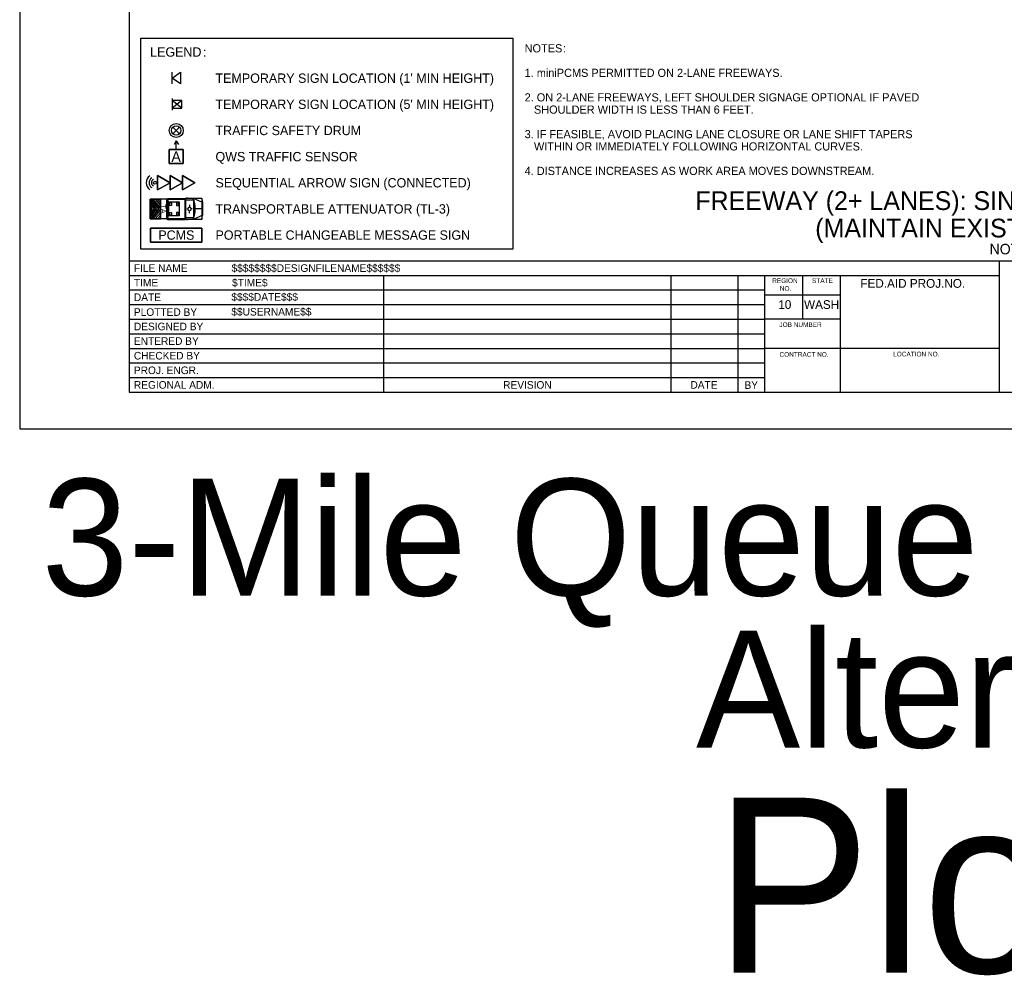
# Model space of a CAD drawing. Extents: x 99999 to 100116, y 99995 to 100013.
# Drawn here: x 100019.06 to 100027.5, y 99995.01 to 100003.19 of the extents above; entities that cross this region are included whole.
import ezdxf

# ---------------------------------------------------------------- set-up
doc = ezdxf.new("R2010")
doc.units = 0
for name, color, linetype in [('SH_DE_DetailHeading1Text', 7, 'Continuous'), ('SH_GI_GeneralNotesBodyText', 7, 'Continuous'), ('SH_GI_PlotLimits', 7, 'Continuous'), ('SH_GI_SheetBorder', 7, 'Continuous'), ('SH_GI_SheetLocationText', 7, 'Continuous'), ('SH_GI_SheetTextInCells', 7, 'Continuous'), ('SH_GI_TitleBlockText', 7, 'Continuous'), ('TR_WZ_PCMS', 7, 'Continuous'), ('TR_WZ_PortableSignMount5ftMinBlk-Wht', 7, 'Continuous'), ('TR_WZ_PortableSignMountBlk-Wht', 7, 'Continuous'), ('TR_WZ_SequentialArrowSign', 7, 'Continuous'), ('TR_WZ_TrafficSafetyDrum', 7, 'Continuous'), ('TR_WZ_TransportableAttenuator', 7, 'Continuous'), ('TR_WZ_WorkZoneDetails', 7, 'Continuous'), ('TR_WZ_WorkZoneTextCurrent', 7, 'Continuous')]:
    doc.layers.add(name, color=color, linetype=linetype)

msp = doc.modelspace()

# ---------------------------------------------------------------- linework, layer by layer
at = {"layer": 'SH_GI_PlotLimits'}
msp.add_lwpolyline([(100019.0625, 99999.6875), (100036.0625, 99999.6875), (100036.0625, 100010.6875), (100019.0625, 100010.6875)], close=True, dxfattribs=at)
at = {"layer": 'SH_GI_SheetBorder'}
for p, q in [((100020, 100010.375), (100020, 100000)), ((100020, 100001.1259), (100035.75, 100001.1259)), ((100027.4566, 100000), (100027.4566, 100001.1259)), ((100020, 100001.0008), (100027.4566, 100001.0008)), ((100022.179, 100001.0008), (100022.179, 100000)), ((100024.641, 100001.0008), (100024.641, 100000)), ((100025.2164, 100001.0008), (100025.2164, 100000)), ((100025.4451, 100001.0008), (100025.4451, 100000)), ((100025.7719, 100000.6255), (100025.7719, 100001.0008)), ((100026.0956, 100000), (100026.0956, 100001.0008)), ((100020, 100000.8757), (100022.1821, 100000.8757)), ((100022.1821, 100000.8757), (100025.4466, 100000.8757)), ((100026.0958, 100000.831), (100025.4466, 100000.831)), ((100020, 100000.7506), (100022.1821, 100000.7506)), ((100022.1821, 100000.7506), (100025.4466, 100000.7506)), ((100020, 100000.6255), (100025.4466, 100000.6255)), ((100026.0958, 100000.6255), (100025.4466, 100000.6255)), ((100020, 100000.5004), (100025.4466, 100000.5004)), ((100020, 100000.3753), (100025.4466, 100000.3753)), ((100027.4566, 100000.3753), (100025.4466, 100000.3753)), ((100020, 100000.2502), (100025.4466, 100000.2502)), ((100020, 100000.1251), (100025.4466, 100000.1251)), ((100020, 100000), (100035.75, 100000))]:
    msp.add_line(p, q, dxfattribs=at)
at = {"layer": 'TR_WZ_PCMS'}
for points in [[(100020.6241, 100001.4059), (100020.6241, 100001.2859), (100020.1841, 100001.2859), (100020.1841, 100001.4059), (100020.6241, 100001.4059)], [(100020.1841, 100001.4059), (100020.1841, 100001.2859), (100020.6241, 100001.2859), (100020.6241, 100001.4059), (100020.1841, 100001.4059)]]:
    msp.add_lwpolyline(points, dxfattribs=at)
at = {"layer": 'TR_WZ_PortableSignMount5ftMinBlk-Wht'}
for p, q in [((100020.3682, 100002.5159), (100020.3682, 100002.4159)), ((100020.4516, 100002.4334), (100020.3682, 100002.4984)), ((100020.4516, 100002.4984), (100020.3682, 100002.4334)), ((100020.4099, 100002.4659), (100020.4099, 100002.4659)), ((100020.41, 100002.4658), (100020.41, 100002.4658))]:
    msp.add_line(p, q, dxfattribs=at)
msp.add_lwpolyline([(100020.4516, 100002.4334), (100020.4516, 100002.4984), (100020.3682, 100002.4984), (100020.3682, 100002.4334)], close=True, dxfattribs=at)
at = {"layer": 'TR_WZ_PortableSignMountBlk-Wht'}
msp.add_line((100020.3682, 100002.64), (100020.3682, 100002.74), dxfattribs=at)
msp.add_lwpolyline([(100020.3682, 100002.6899), (100020.44, 100002.74), (100020.44, 100002.64)], close=True, dxfattribs=at)
at = {"layer": 'TR_WZ_SequentialArrowSign'}
for points in [[(100020.3508, 100001.7939), (100020.2441, 100001.7321), (100020.2441, 100001.8557), (100020.3508, 100001.7939)], [(100020.2441, 100001.8557), (100020.2441, 100001.7321), (100020.3508, 100001.7939), (100020.2441, 100001.8557)], [(100020.4575, 100001.7939), (100020.3508, 100001.7321), (100020.3508, 100001.7939), (100020.3508, 100001.8557), (100020.4575, 100001.7939)], [(100020.3508, 100001.8557), (100020.3508, 100001.7939), (100020.3508, 100001.7321), (100020.4575, 100001.7939), (100020.3508, 100001.8557)], [(100020.5641, 100001.7939), (100020.4575, 100001.7321), (100020.4575, 100001.7939), (100020.4575, 100001.8557), (100020.5641, 100001.7939)], [(100020.4575, 100001.8557), (100020.4575, 100001.7939), (100020.4575, 100001.7321), (100020.5641, 100001.7939), (100020.4575, 100001.8557)]]:
    msp.add_lwpolyline(points, dxfattribs=at)
msp.add_circle((100020.2216, 100001.7939), 0.0125, dxfattribs=at)
for radius, start, end in [(0.075, 127.32912, 232.67088), (0.05, 123.97816, 236.02184), (0.03, 117.15796, 242.84204)]:
    msp.add_arc((100020.2216, 100001.7939), radius, start, end, dxfattribs=at)
at = {"layer": 'TR_WZ_TrafficSafetyDrum'}
for p, q in [((100020.4324, 100002.2701), (100020.3758, 100002.2136)), ((100020.4324, 100002.2136), (100020.3758, 100002.2701))]:
    msp.add_line(p, q, dxfattribs=at)
for radius in [0.06, 0.06, 0.04]:
    msp.add_circle((100020.4041, 100002.2419), radius, dxfattribs=at)
at = {"layer": 'TR_WZ_TransportableAttenuator'}
for p, q in [((100020.1791, 100001.6385), (100020.2355, 100001.5706)), ((100020.1791, 100001.6167), (100020.1791, 100001.6385)), ((100020.2355, 100001.5706), (100020.1791, 100001.6385)), ((100020.1791, 100001.6385), (100020.1791, 100001.6167)), ((100020.2551, 100001.5701), (100020.185, 100001.6546)), ((100020.185, 100001.6546), (100020.2041, 100001.6546)), ((100020.185, 100001.6546), (100020.2551, 100001.5701)), ((100020.2041, 100001.6546), (100020.185, 100001.6546)), ((100020.2041, 100001.6546), (100020.2676, 100001.5776)), ((100020.2676, 100001.5776), (100020.2041, 100001.6546)), ((100020.2676, 100001.6025), (100020.2248, 100001.6546)), ((100020.2248, 100001.6546), (100020.2439, 100001.6546)), ((100020.2439, 100001.6546), (100020.2248, 100001.6546)), ((100020.2248, 100001.6546), (100020.2676, 100001.6025)), ((100020.2439, 100001.6546), (100020.2676, 100001.626)), ((100020.2676, 100001.626), (100020.2439, 100001.6546)), ((100020.2676, 100001.4857), (100020.2676, 100001.6546)), ((100020.3279, 100001.6546), (100020.2676, 100001.6546)), ((100020.3208, 100001.6515), (100020.3208, 100001.4884)), ((100020.3241, 100001.657), (100020.3274, 100001.657)), ((100020.3274, 100001.657), (100020.3274, 100001.4829)), ((100020.3279, 100001.6599), (100020.4803, 100001.6599)), ((100020.3279, 100001.6599), (100020.3279, 100001.4799)), ((100020.3279, 100001.6543), (100020.3279, 100001.4857)), ((100020.3323, 100001.6528), (100020.3323, 100001.4871)), ((100020.3323, 100001.6528), (100020.476, 100001.6528)), ((100020.476, 100001.6528), (100020.476, 100001.4871)), ((100020.4803, 100001.6599), (100020.4803, 100001.4799)), ((100020.4824, 100001.6599), (100020.4824, 100001.4799)), ((100020.6223, 100001.6599), (100020.4824, 100001.6599)), ((100020.551, 100001.646), (100020.4824, 100001.646)), ((100020.5014, 100001.6625), (100020.493, 100001.6625)), ((100020.551, 100001.6599), (100020.5421, 100001.646)), ((100020.551, 100001.6599), (100020.551, 100001.4799)), ((100020.5523, 100001.6599), (100020.5523, 100001.4799)), ((100020.6223, 100001.627), (100020.5523, 100001.6599)), ((100020.6223, 100001.6599), (100020.6223, 100001.4799)), ((100020.6223, 100001.6599), (100020.6291, 100001.6236)), ((100020.2174, 100001.5709), (100020.1791, 100001.6167)), ((100020.1791, 100001.6167), (100020.2174, 100001.5709)), ((100020.1791, 100001.5935), (100020.1987, 100001.5702)), ((100020.1791, 100001.5467), (100020.1791, 100001.5935)), ((100020.1987, 100001.5702), (100020.1791, 100001.5935)), ((100020.1791, 100001.5935), (100020.1791, 100001.5467)), ((100020.1791, 100001.5248), (100020.2174, 100001.5709)), ((100020.2174, 100001.5709), (100020.1791, 100001.5248)), ((100020.2355, 100001.5706), (100020.1791, 100001.5027)), ((100020.1791, 100001.5027), (100020.2355, 100001.5706)), ((100020.1987, 100001.5702), (100020.1791, 100001.5467)), ((100020.1791, 100001.5467), (100020.1987, 100001.5702)), ((100020.1849, 100001.4855), (100020.2551, 100001.5701)), ((100020.2551, 100001.5701), (100020.1849, 100001.4855)), ((100020.2676, 100001.5625), (100020.2037, 100001.4855)), ((100020.2037, 100001.4855), (100020.2676, 100001.5625)), ((100020.2676, 100001.626), (100020.2676, 100001.6025)), ((100020.2676, 100001.6025), (100020.2676, 100001.626)), ((100020.2676, 100001.5776), (100020.2676, 100001.5625)), ((100020.2676, 100001.5625), (100020.2676, 100001.5776)), ((100020.3208, 100001.5826), (100020.3274, 100001.5793)), ((100020.3208, 100001.5573), (100020.3274, 100001.5607)), ((100020.3226, 100001.57), (100020.3257, 100001.57)), ((100020.3241, 100001.5725), (100020.3241, 100001.5674)), ((100020.4951, 100001.5701), (100020.5045, 100001.57)), ((100020.507, 100001.5696), (100020.507, 100001.5696)), ((100020.5175, 100001.6056), (100020.5175, 100001.5911)), ((100020.5398, 100001.5701), (100020.5305, 100001.57)), ((100020.6223, 100001.57), (100020.566, 100001.57)), ((100020.6291, 100001.6236), (100020.6291, 100001.5163)), ((100020.1791, 100001.5027), (100020.1791, 100001.5248)), ((100020.1791, 100001.5248), (100020.1791, 100001.5027)), ((100020.2037, 100001.4855), (100020.1849, 100001.4855)), ((100020.1849, 100001.4855), (100020.2037, 100001.4855)), ((100020.2243, 100001.4855), (100020.2676, 100001.5376)), ((100020.2676, 100001.5376), (100020.2243, 100001.4855)), ((100020.2446, 100001.4855), (100020.2243, 100001.4855)), ((100020.2243, 100001.4855), (100020.2446, 100001.4855)), ((100020.2676, 100001.5128), (100020.2446, 100001.4855)), ((100020.2446, 100001.4855), (100020.2676, 100001.5128)), ((100020.2676, 100001.5376), (100020.2676, 100001.5128)), ((100020.2676, 100001.5128), (100020.2676, 100001.5376)), ((100020.3279, 100001.4857), (100020.2676, 100001.4857)), ((100020.3241, 100001.4829), (100020.3274, 100001.4829)), ((100020.3279, 100001.4799), (100020.4803, 100001.4799)), ((100020.3323, 100001.4871), (100020.476, 100001.4871)), ((100020.551, 100001.4939), (100020.4824, 100001.4939)), ((100020.6223, 100001.4799), (100020.4824, 100001.4799)), ((100020.5014, 100001.4774), (100020.493, 100001.4774)), ((100020.5175, 100001.5343), (100020.5175, 100001.5488)), ((100020.5437, 100001.4939), (100020.551, 100001.4799)), ((100020.6223, 100001.5129), (100020.5523, 100001.4799)), ((100020.6223, 100001.4799), (100020.6291, 100001.5163))]:
    msp.add_line(p, q, dxfattribs=at)
for points in [[(100020.2676, 100001.4855), (100020.1791, 100001.4855), (100020.1791, 100001.6546), (100020.2676, 100001.6546)], [(100020.3398, 100001.63), (100020.4298, 100001.63), (100020.4298, 100001.51), (100020.3398, 100001.51)], [(100020.3473, 100001.6225), (100020.3623, 100001.6225), (100020.3623, 100001.6), (100020.3473, 100001.6)], [(100020.4223, 100001.6225), (100020.4073, 100001.6225), (100020.4073, 100001.6), (100020.4223, 100001.6)], [(100020.3473, 100001.54), (100020.3623, 100001.54), (100020.3623, 100001.5175), (100020.3473, 100001.5175)], [(100020.4223, 100001.54), (100020.4073, 100001.54), (100020.4073, 100001.5175), (100020.4223, 100001.5175)]]:
    msp.add_lwpolyline(points, close=True, dxfattribs=at)
msp.add_lwpolyline([(100020.2676, 100001.6546), (100020.1791, 100001.6546), (100020.1791, 100001.4855), (100020.2676, 100001.4857)], dxfattribs=at)
for centre, major_axis, start_param, end_param in [((100020.3241, 100001.6515), (0, 0.00549), 6.283185, 7.853982), ((100020.4523, 100001.5699), (0, 0.1889), 4.215852, 5.209111), ((100020.3241, 100001.4884), (0, -0.00549), 4.712389, 6.283185)]:
    msp.add_ellipse(centre, major_axis=major_axis, ratio=0.60201, start_param=start_param, end_param=end_param, dxfattribs=at)
for centre, major_axis in [((100020.3241, 100001.5699), (0, -0.00254)), ((100020.5175, 100001.5699), (0, -0.0173))]:
    msp.add_ellipse(centre, major_axis=major_axis, ratio=0.60201, dxfattribs=at)
at = {"layer": 'TR_WZ_WorkZoneDetails'}
for p, q in [((100020.4041, 100002.1529), (100020.3854, 100002.1204)), ((100020.4041, 100002.0779), (100020.4041, 100002.1529)), ((100020.4041, 100002.1529), (100020.4229, 100002.1204))]:
    msp.add_line(p, q, dxfattribs=at)
msp.add_lwpolyline([(100020.3441, 100002.0779), (100020.4641, 100002.0779), (100020.4641, 100001.9579), (100020.3441, 100001.9579)], close=True, dxfattribs=at)
msp.add_lwpolyline([(100020.3441, 100002.0779), (100020.3441, 100001.9579), (100020.4641, 100001.9579), (100020.4641, 100002.0779), (100020.4041, 100002.0779), (100020.3441, 100002.0779)], dxfattribs=at)
at = {"layer": 'TR_WZ_WorkZoneTextCurrent'}
msp.add_lwpolyline([(100020.1, 100003.0339), (100023.2886, 100003.0339), (100023.2886, 100001.2259), (100020.1, 100001.2259)], close=True, dxfattribs=at)

# ---------------------------------------------------------------- texts
at = {"layer": 'SH_DE_DetailHeading1Text'}
for s, height, p in [('FREEWAY (2+ LANES): SINGLE LEFT LANE CLOSURE', 0.16, (100024.8508, 100001.5606)), ('(MAINTAIN EXISTING SPEED LIMIT)', 0.16, (100025.8785, 100001.3259)), ('NOT TO SCALE', 0.09, (100027.3725, 100001.1809))]:
    msp.add_text(s, height=height, rotation=360, dxfattribs=at).set_placement(p)
at = {"layer": 'SH_GI_GeneralNotesBodyText'}
for s, p in [('NOTES', (100023.3886, 100002.9106)), (':', (100023.7161, 100002.9106)), ('1. miniPCMS PERMITTED ON 2-LANE FREEWAYS.', (100023.3886, 100002.7006)), ('2. ON 2-LANE FREEWAYS, LEFT SHOULDER SIGNAGE OPTIONAL IF PAVED ', (100023.3886, 100002.4906)), ('SHOULDER WIDTH IS LESS THAN 6 FEET.', (100023.4686, 100002.3856)), ('3. IF FEASIBLE, AVOID PLACING LANE CLOSURE OR LANE SHIFT TAPERS ', (100023.3886, 100002.1756)), ('WITHIN OR IMMEDIATELY FOLLOWING HORIZONTAL CURVES.', (100023.4686, 100002.0706)), ('4. DISTANCE INCREASES AS WORK AREA MOVES DOWNSTREAM.', (100023.3886, 100001.8606))]:
    msp.add_text(s, height=0.07, rotation=360, dxfattribs=at).set_placement(p)
at = {"layer": 'SH_GI_SheetLocationText'}
for s, height, p in [('3-Mile Queue Warning System', 1, (100019.2499, 99998.258)), ('Alternative', 1, (100024.8575, 99996.9562)), ('Plot 2', 1.5, (100025.015, 99995.0267))]:
    msp.add_text(s, height=height, dxfattribs=at).set_placement(p)
at = {"layer": 'SH_GI_SheetTextInCells'}
for s, height, p in [('FILE NAME', 0.06505, (100020.041, 100001.0308)), ('TIME', 0.06505, (100020.041, 100000.9057)), ('REGION', 0.04003, (100025.5099, 100000.9352)), ('STATE', 0.04003, (100025.8511, 100000.9357)), ('FED.AID PROJ.NO.', 0.07506, (100026.2652, 100000.8945)), ('NO.', 0.04003, (100025.5752, 100000.869)), ('DATE', 0.06505, (100020.041, 100000.7806)), ('PLOTTED BY', 0.06505, (100020.041, 100000.6538)), ('10', 0.07506, (100025.5621, 100000.7131)), ('WASH', 0.07506, (100025.7826, 100000.7131)), ('DESIGNED BY', 0.065052, (100020.041, 100000.5304)), ('JOB NUMBER', 0.04003, (100025.5712, 100000.5587)), ('ENTERED BY', 0.06505, (100020.041, 100000.4053)), ('CHECKED BY', 0.06505, (100020.041, 100000.2802)), ('CONTRACT NO.', 0.040032, (100025.5725, 100000.3037)), ('LOCATION NO.', 0.040032, (100026.5465, 100000.3067)), ('PROJ. ENGR.', 0.065052, (100020.041, 100000.1551)), ('REGIONAL ADM.', 0.065052, (100020.041, 100000.03)), ('REVISION', 0.06505, (100023.2048, 100000.03)), ('DATE', 0.06505, (100024.8091, 100000.03)), ('BY', 0.06505, (100025.2725, 100000.0285))]:
    msp.add_text(s, height=height, dxfattribs=at).set_placement(p)
at = {"layer": 'SH_GI_TitleBlockText'}
for s, height, p in [('$$$$$$$$DESIGNFILENAME$$$$$$', 0.065052, (100020.8775, 100001.0308)), ('$TIME$', 0.06505, (100020.882, 100000.9059)), ('$$$$DATE$$$', 0.065052, (100020.8759, 100000.7835)), ('$$USERNAME$$', 0.065052, (100020.8759, 100000.6567))]:
    msp.add_text(s, height=height, dxfattribs=at).set_placement(p)
at = {"layer": 'TR_WZ_PCMS'}
msp.add_text('PCMS', height=0.08, rotation=360, dxfattribs=at).set_placement((100020.2502, 100001.3059))
at = {"layer": 'TR_WZ_TransportableAttenuator'}
msp.add_text('TA', height=0.045, rotation=269.99999, dxfattribs=at).set_placement((100020.2717, 100001.6094))
at = {"layer": 'TR_WZ_WorkZoneDetails'}
msp.add_text('A', height=0.09, dxfattribs=at).set_placement((100020.3625, 100001.9729))
at = {"layer": 'TR_WZ_WorkZoneTextCurrent'}
for s, p in [('LEGEND', (100020.18, 100002.8739)), (':', (100020.6328, 100002.8739)), ("TEMPORARY SIGN LOCATION (1' MIN HEIGHT)", (100020.74, 100002.6499)), ("TEMPORARY SIGN LOCATION (5' MIN HEIGHT)", (100020.74, 100002.4259)), ('TRAFFIC SAFETY DRUM', (100020.74, 100002.2019)), ('QWS TRAFFIC SENSOR', (100020.74, 100001.9779)), ('SEQUENTIAL ARROW SIGN (CONNECTED)', (100020.74, 100001.7539)), ('TRANSPORTABLE ATTENUATOR (TL-3)', (100020.74, 100001.5299)), ('PORTABLE CHANGEABLE MESSAGE SIGN', (100020.74, 100001.3059))]:
    msp.add_text(s, height=0.08, rotation=360, dxfattribs=at).set_placement(p)

doc.saveas('drawing.dxf')
